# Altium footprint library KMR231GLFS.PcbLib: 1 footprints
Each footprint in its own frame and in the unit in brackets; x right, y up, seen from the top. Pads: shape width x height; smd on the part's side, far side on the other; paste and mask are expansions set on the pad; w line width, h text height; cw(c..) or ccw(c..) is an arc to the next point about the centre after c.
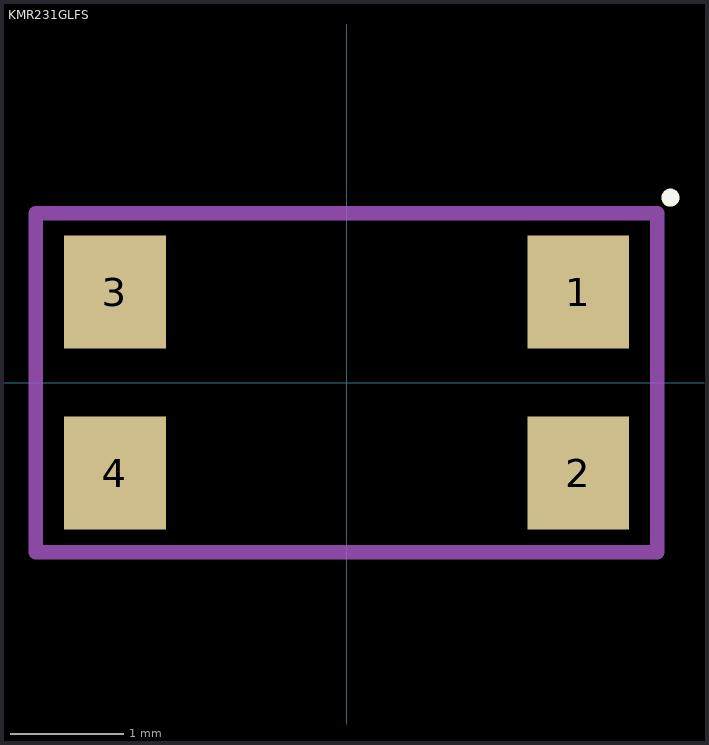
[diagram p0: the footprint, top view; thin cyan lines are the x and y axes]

## KMR231GLFS [mm]
pads (4):
  rect 0.9x1 smd: 1(2.05,0.8) 2(2.05,-0.8) 3(-2.05,0.8) 4(-2.05,-0.8)
Top Overlay:
  circle w0.127: c2.867,1.637 r0.016
Mechanical 13:
  lines w0.127: -2.75,-1.5 -2.75,1.5 2.75,1.5 2.75,-1.5 -2.75,-1.5
3D body "KMR231GLFS.STEP": height 1.9, standoff 0, extent -2.317,-1.401 2.283,1.399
